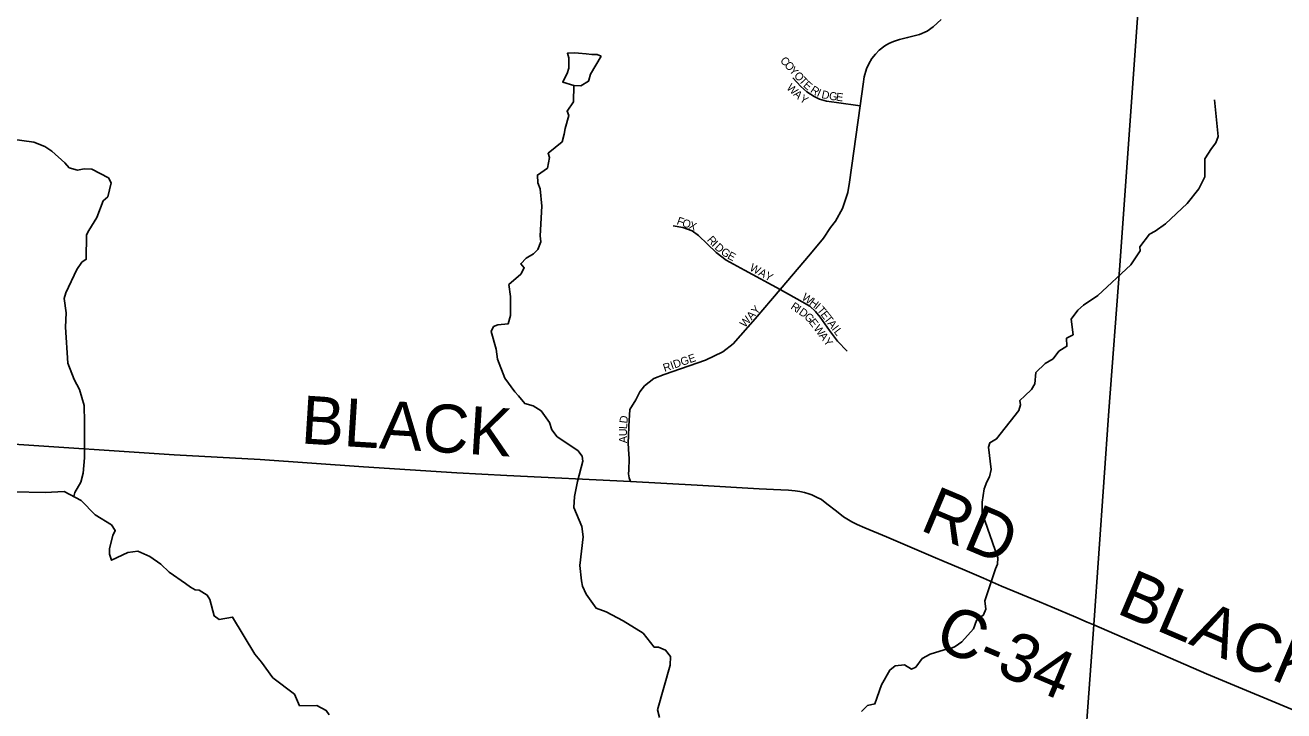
# Model space of a CAD drawing. Extents: x 0 to 40.4, y 0 to 22.
# Drawn here: x 3.509 to 4.998, y 18.913 to 19.724 of the extents above; entities that cross this region are included whole.
import ezdxf

# ---------------------------------------------------------------- set-up
doc = ezdxf.new("R2010")
doc.units = 0
for name, color, linetype in [('GM_X_County_Road', 7, 'Continuous'), ('GM_X_County_Road_Text', 7, 'Continuous'), ('GM_X_Minor_Lake', 7, 'Continuous'), ('GM_X_Minor_River', 7, 'Continuous'), ('GM_X_State_Route', 7, 'Continuous'), ('GM_X_Township_Road', 7, 'Continuous'), ('GM_X_Township_Road_Text', 7, 'Continuous'), ('GM_X_Township_Subdivision', 7, 'Continuous'), ('GM_X_Township_Subdivision_Text', 7, 'Continuous')]:
    doc.layers.add(name, color=color, linetype=linetype)

msp = doc.modelspace()

# ---------------------------------------------------------------- linework, layer by layer
at = {"layer": 'GM_X_County_Road'}
msp.add_lwpolyline([(4.7732, 19.0147), (4.7654, 19.018), (4.7519, 19.0239), (4.724, 19.0357), (4.709, 19.0421), (4.6642, 19.0606), (4.643, 19.0698), (4.6182, 19.0805), (4.5964, 19.0896), (4.5835, 19.0952), (4.5585, 19.1058), (4.5282, 19.119), (4.5024, 19.1295), (4.4932, 19.1334), (4.4869, 19.1364), (4.4773, 19.1426), (4.4688, 19.1491), (4.4576, 19.1578), (4.451, 19.1628), (4.4454, 19.1659), (4.4396, 19.1685), (4.4363, 19.1698), (4.4309, 19.1713), (4.4255, 19.1723), (4.4199, 19.1733), (4.4121, 19.1741), (4.403, 19.1745), (4.3773, 19.1758), (4.3041, 19.1798), (4.2253, 19.1842), (4.079, 19.1912), (4.0198, 19.1947), (3.9095, 19.2015), (3.787, 19.2102), (3.6855, 19.2158), (3.4837, 19.2291)], dxfattribs=at)
at = {"layer": 'GM_X_Minor_Lake'}
for points in [[(4.1907, 19.6872), (4.1858, 19.6892), (4.1793, 19.6892), (4.1729, 19.69), (4.1638, 19.6911), (4.1584, 19.6912), (4.1505, 19.6908), (4.1524, 19.6855), (4.1523, 19.673), (4.1504, 19.6669), (4.1477, 19.6616), (4.1451, 19.6567), (4.1583, 19.6525)], [(4.1583, 19.6525), (4.1663, 19.6521), (4.1754, 19.6577), (4.1758, 19.6589), (4.1781, 19.6661), (4.1907, 19.6872)]]:
    msp.add_lwpolyline(points, dxfattribs=at)
at = {"layer": 'GM_X_Minor_River'}
for points in [[(4.1183, 19.4747), (4.1203, 19.51), (4.1184, 19.5305), (4.1154, 19.5377), (4.1151, 19.5468), (4.1269, 19.5551), (4.1292, 19.5676), (4.1277, 19.5726), (4.1444, 19.5862), (4.1467, 19.5952), (4.1479, 19.6017), (4.1521, 19.6172), (4.1502, 19.6222), (4.1579, 19.6335), (4.1583, 19.6525)], [(4.4987, 18.9121), (4.5056, 18.9192), (4.5143, 18.9211), (4.5223, 18.9438), (4.5319, 18.9612), (4.5384, 18.9661), (4.5494, 18.9676), (4.5577, 18.9623), (4.5626, 18.9645), (4.5702, 18.9748), (4.5798, 18.98), (4.5965, 18.9853), (4.6014, 18.9856), (4.6094, 18.989), (4.6174, 18.9947), (4.6311, 19.0102), (4.6345, 19.02), (4.6429, 19.0265), (4.6456, 19.0333), (4.6445, 19.0431), (4.6571, 19.081), (4.6594, 19.0863), (4.6598, 19.0939), (4.6414, 19.1474), (4.6411, 19.16), (4.6438, 19.1755), (4.6468, 19.1838), (4.6499, 19.1899), (4.6518, 19.1986), (4.6489, 19.2248), (4.6504, 19.2301), (4.6584, 19.2346), (4.6847, 19.2683), (4.6866, 19.2751), (4.6859, 19.28), (4.6916, 19.2857), (4.6996, 19.2932), (4.7034, 19.2997), (4.7049, 19.3133), (4.716, 19.3239), (4.7251, 19.3292), (4.732, 19.3386), (4.7415, 19.3443), (4.7411, 19.3538), (4.7491, 19.3579), (4.7465, 19.3761), (4.7545, 19.3871), (4.761, 19.3928), (4.7781, 19.4041), (4.8173, 19.4407), (4.8283, 19.457), (4.828, 19.4619), (4.8394, 19.4767), (4.8459, 19.4805), (4.858, 19.4891), (4.8839, 19.5133), (4.8976, 19.5303), (4.9049, 19.5447), (4.9046, 19.566), (4.9126, 19.5781), (4.9176, 19.5849), (4.9206, 19.5924), (4.9162, 19.6357)], [(3.5667, 19.1666), (3.5679, 19.1714), (3.5748, 19.1835), (3.5775, 19.1941), (3.5791, 19.2123), (3.5792, 19.2544), (3.5789, 19.2742), (3.5733, 19.2931), (3.5669, 19.3049), (3.5597, 19.3243), (3.5568, 19.3668), (3.5576, 19.3838), (3.5554, 19.4009), (3.557, 19.4074), (3.57, 19.435), (3.5761, 19.4437), (3.5814, 19.4471), (3.5815, 19.4759), (3.5842, 19.4812), (3.5937, 19.4964), (3.6013, 19.5164), (3.6067, 19.521), (3.6109, 19.5376), (3.6075, 19.5433), (3.5878, 19.5537), (3.5787, 19.5541), (3.5711, 19.5526), (3.5613, 19.5553), (3.556, 19.5614), (3.5405, 19.5751), (3.5325, 19.5804), (3.5193, 19.5858), (3.4935, 19.5893)], [(4.2597, 18.9053), (4.2571, 18.9141), (4.272, 18.9671), (4.2725, 18.9773), (4.2668, 18.9846), (4.2585, 18.9884), (4.2532, 18.9884), (4.2403, 19.0048), (4.2165, 19.0193), (4.1964, 19.03), (4.1846, 19.0346), (4.1726, 19.0509), (4.1684, 19.0604), (4.1673, 19.0669), (4.1651, 19.0851), (4.1694, 19.1188), (4.1675, 19.131), (4.1581, 19.1534), (4.1589, 19.1666), (4.1624, 19.1841), (4.1689, 19.2083), (4.1682, 19.2144), (4.1629, 19.2209), (4.1383, 19.2372), (4.1323, 19.2452), (4.1293, 19.254), (4.1194, 19.2677), (4.11, 19.2738), (4.1001, 19.2765), (4.0926, 19.2856), (4.0884, 19.2905), (4.0767, 19.3065), (4.0677, 19.3289), (4.0662, 19.3407), (4.0602, 19.3616), (4.0633, 19.3676), (4.0682, 19.3695), (4.0803, 19.3706), (4.0834, 19.3808), (4.0831, 19.4032), (4.0813, 19.4172), (4.0953, 19.4297), (4.0995, 19.4369), (4.0954, 19.4418), (4.1018, 19.4486), (4.1106, 19.4535), (4.1155, 19.4588), (4.119, 19.4679), (4.1183, 19.4747)], [(3.8686, 18.9083), (3.8652, 18.9136), (3.8542, 18.9193), (3.8337, 18.919), (3.8277, 18.9327), (3.802, 18.9521), (3.7888, 18.9704), (3.7808, 18.9799), (3.7544, 19.024), (3.7385, 19.021), (3.7328, 19.0252), (3.7276, 19.0446), (3.7245, 19.0499), (3.7151, 19.0556), (3.7102, 19.056), (3.7045, 19.0594), (3.6988, 19.0636), (3.6795, 19.077), (3.6697, 19.0865), (3.6564, 19.0956), (3.6424, 19.1017), (3.6306, 19.1003), (3.6113, 19.0912), (3.609, 19.0985), (3.609, 19.1049), (3.6129, 19.1204), (3.6156, 19.1265), (3.6114, 19.133), (3.5917, 19.1448), (3.5755, 19.1619), (3.5554, 19.1726), (3.5326, 19.1712), (3.4943, 19.1721)]]:
    msp.add_lwpolyline(points, dxfattribs=at)
at = {"layer": 'GM_X_State_Route'}
msp.add_lwpolyline([(4.8369, 19.8987), (4.804, 19.4399), (4.791, 19.2678), (4.7732, 19.0147), (4.7573, 18.794), (4.7539, 18.7281), (4.7525, 18.6596), (4.7554, 18.5304), (4.7572, 18.4214), (4.7597, 18.2646), (4.7608, 18.2263), (4.759, 18.178), (4.7164, 17.9544), (4.6792, 17.7593)], dxfattribs=at)
at = {"layer": 'GM_X_Township_Road'}
msp.add_lwpolyline([(5.6523, 18.5981), (5.6383, 18.6088), (5.6308, 18.6183), (5.6228, 18.629), (5.6164, 18.6385), (5.613, 18.6427), (5.6073, 18.6461), (5.602, 18.6499), (5.5952, 18.6538), (5.5815, 18.6587), (5.3372, 18.7645), (5.1471, 18.8565), (4.9066, 18.9567), (4.7732, 19.0147)], dxfattribs=at)
at = {"layer": 'GM_X_Township_Subdivision'}
for points in [[(4.2253, 19.1842), (4.2236, 19.1888), (4.2228, 19.1933), (4.2231, 19.1977), (4.2237, 19.211), (4.2234, 19.2171), (4.2229, 19.2221), (4.2226, 19.2305), (4.223, 19.2378), (4.2232, 19.2498), (4.2245, 19.2696), (4.2316, 19.2809), (4.2362, 19.2902), (4.2418, 19.2973), (4.253, 19.306), (4.2649, 19.3109), (4.3138, 19.3277), (4.3343, 19.3376), (4.3468, 19.3473), (4.3728, 19.3767), (4.4021, 19.4112), (4.4383, 19.4537), (4.4537, 19.472), (4.4619, 19.4846), (4.4679, 19.4924), (4.4762, 19.5072), (4.4823, 19.526), (4.4843, 19.5385), (4.4968, 19.6286), (4.5003, 19.6544), (4.5017, 19.6631), (4.5044, 19.6725), (4.507, 19.6783), (4.5108, 19.6845), (4.5151, 19.6899), (4.5195, 19.6943), (4.5263, 19.6995), (4.5309, 19.7022), (4.5364, 19.7047), (4.5436, 19.7071), (4.5531, 19.7094), (4.5592, 19.711), (4.5673, 19.7132), (4.5762, 19.7171), (4.5835, 19.7219), (4.5927, 19.7309)], [(4.4968, 19.6286), (4.4689, 19.6325), (4.4573, 19.6342), (4.4489, 19.6366), (4.4424, 19.6396), (4.4337, 19.6452), (4.4269, 19.6515), (4.4174, 19.6619)], [(4.2757, 19.4865), (4.2872, 19.4849), (4.2981, 19.4808), (4.3058, 19.4751), (4.3162, 19.465), (4.3267, 19.455), (4.3386, 19.4462), (4.36, 19.4344), (4.4021, 19.4112)], [(4.4021, 19.4112), (4.4282, 19.3968), (4.4372, 19.3915), (4.4441, 19.3855), (4.4498, 19.3786), (4.4605, 19.363), (4.4703, 19.3502), (4.4814, 19.3384)]]:
    msp.add_lwpolyline(points, dxfattribs=at)

# ---------------------------------------------------------------- texts
at = {"layer": 'GM_X_County_Road_Text'}
for s, rotation, p in [('BLACK', 356.3857, (3.8344, 19.2294)), ('RD', 337.1927, (4.5661, 19.1275)), ('C-34', 337.1188, (4.5823, 18.9888))]:
    msp.add_text(s, height=0.05682, rotation=rotation, dxfattribs=at).set_placement(p)
at = {"layer": 'GM_X_Township_Road_Text'}
msp.add_text('BLACKS', height=0.05682, rotation=336.915, dxfattribs=at).set_placement((4.7986, 19.0291))
at = {"layer": 'GM_X_Township_Subdivision_Text'}
for s, rotation, p in [('C', 312.5612, (4.4016, 19.6816)), ('O', 312.5472, (4.4067, 19.6761)), ('Y', 312.5631, (4.4123, 19.6699)), ('W', 315.2377, (4.4092, 19.6493)), ('O', 312.5631, (4.418, 19.6638)), ('T', 313.0012, (4.4237, 19.6576)), ('E', 318.5213, (4.4289, 19.652)), ('A', 317.7415, (4.4172, 19.6414)), ('Y', 325.4224, (4.4245, 19.6349)), ('R', 327.1234, (4.4372, 19.6452)), ('I', 336.1756, (4.4449, 19.6403)), ('D', 347.3085, (4.4506, 19.638)), ('G', 352.5191, (4.4597, 19.636)), ('E', 352.5775, (4.4679, 19.6349)), ('F', 340.563, (4.2792, 19.4888)), ('O', 340.5746, (4.2855, 19.4865)), ('X', 338.4665, (4.2933, 19.4838)), ('R', 311.2019, (4.3152, 19.4697)), ('I', 314.9085, (4.3206, 19.4635)), ('D', 318.4449, (4.324, 19.4601)), ('G', 325.1133, (4.3312, 19.4539)), ('E', 331.9462, (4.3391, 19.4485)), ('WAY', 331.1146, (4.3653, 19.4345)), ('W', 325.0975, (4.4271, 19.4002)), ('WAY', 48.4936, (4.3606, 19.3657)), ('R', 326.3032, (4.4139, 19.3892)), ('I', 326.0676, (4.4202, 19.385)), ('D', 324.9095, (4.4236, 19.3827)), ('H', 322.999, (4.436, 19.3941)), ('I', 318.4935, (4.4425, 19.3892)), ('T', 310.0679, (4.4453, 19.3867)), ('G', 315.0309, (4.4301, 19.3782)), ('E', 307.6186, (4.4357, 19.3726)), ('E', 308.0283, (4.4496, 19.3816)), ('T', 307.5419, (4.4537, 19.3764)), ('A', 307.5544, (4.4577, 19.3711)), ('W', 306.4428, (4.4413, 19.3653)), ('A', 306.482, (4.4477, 19.3566)), ('I', 307.5606, (4.4628, 19.3645)), ('L', 307.5419, (4.4653, 19.3612)), ('Y', 307.2503, (4.4528, 19.3498)), ('RIDGE', 19.1319, (4.2656, 19.3138)), ('D', 83.165, (4.2214, 19.2526)), ('U', 89.8907, (4.221, 19.2379)), ('L', 86.6383, (4.2211, 19.2461)), ('A', 89.8907, (4.221, 19.2296))]:
    msp.add_text(s, height=0.00947, rotation=rotation, dxfattribs=at).set_placement(p)

doc.saveas('drawing.dxf')
